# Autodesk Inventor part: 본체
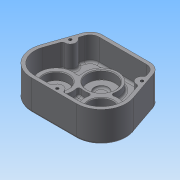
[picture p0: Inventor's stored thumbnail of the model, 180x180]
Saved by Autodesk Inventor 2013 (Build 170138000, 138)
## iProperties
Created: 2014-12
Part Number: 본체
Material: 일반
Document SubType Name: Modeling
Designer: WINDOWS7
Density: 1 g/cm^3
Author: WINDOWS7
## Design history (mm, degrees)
sketch "스케치1" dims "d16" = 46
  geometry: L1 (-47, 36)-(47, 36); L2 (47, 36)-(66.565, -20.803); L3 (32.527, -68.527)-(-32.527, -68.527); L4 (-66.565, -20.803)-(-47, 36); L5 (-32.527, -32.527)-(0, 0); L6 (0, 0)-(32.527, -32.527); L7 (0, 0)-(-87.158, 0); A1 r 36 centre (-32.527, -32.527) between (-32.527, -68.527) and (-66.565, -20.803); A2 r 36 centre (32.527, -32.527) between (66.565, -20.803) and (32.527, -68.527); 2 further points
  constraints: 14 end point, 4 point on circle, 4 tangent, 2 centre point, 2 horizontal, 2 midpoint, 2 vertical alignment, 1 coincident, 1 equal radius, 1 parallel, 3 other
  dimensions: "d8" = 94 distance of L1.start L1.end; "d11" = 36 distance from line of L5.end L1; "d12" = 36 radius of A1; "d13" = 90 deg angle of L6 L5; "d18" = 45 deg angle of L7 L5
extrude "돌출1" new body sketch "스케치1" distance "d19" = 44; taper "d20" = 0 deg
fillet "모깎기1" dims "d21" = 18
sketch "스케치2"
  geometry: L1 (-51.181, 23.862)-(-66.565, -20.803) reference; L2 (-32.527, -68.527)-(32.527, -68.527) reference; L3 (66.565, -20.803)-(51.181, 23.862) reference; L4 (34.162, 36)-(-34.162, 36) reference; L5 (-46.453, 22.233)-(-61.837, -22.432); L6 (-32.527, -63.527)-(32.527, -63.527); L7 (61.837, -22.432)-(46.453, 22.233); L8 (34.162, 31)-(-34.162, 31); A1 r 18 centre (-34.162, 18) between (-34.162, 36) and (-51.181, 23.862) reference; A2 r 36 centre (-32.527, -32.527) between (-66.565, -20.803) and (-32.527, -68.527) reference; A3 r 36 centre (32.527, -32.527) between (32.527, -68.527) and (66.565, -20.803) reference; A4 r 18 centre (34.162, 18) between (51.181, 23.862) and (34.162, 36) reference; A5 r 13 centre (-34.162, 18) between (-34.162, 31) and (-46.453, 22.233); A6 r 31 centre (-32.527, -32.527) between (-61.837, -22.432) and (-32.527, -63.527); A7 r 31 centre (32.527, -32.527) between (32.527, -63.527) and (61.837, -22.432); A8 r 13 centre (34.162, 18) between (46.453, 22.233) and (34.162, 31); 1 further point
  constraints: 8 end point, 8 point on circle, 4 centre point, 7 other
  dimensions: "d22" = 5 distance between parallel lines of L4 L8
extrude "돌출2" cut sketch "스케치2" distance "d23" = 34; taper "d24" = 0 deg
sketch "스케치3"
  geometry: C1 r 24 at (0, 0); C2 r 24 at (-32.527, -32.527); C3 r 24 at (32.527, -32.527); A1 r 31 centre (-32.527, -32.527) between (-61.837, -22.432) and (-32.527, -63.527) reference; A2 r 31 centre (32.527, -32.527) between (32.527, -63.527) and (61.837, -22.432) reference; 1 further point
  constraints: 3 centre point, 3 coincident, 1 equal radius
  dimensions: "d25" = 48 diameter of C1; "d27" = 48 diameter of C3
extrude "돌출3" join sketch "스케치3" distance "d28" = 11; taper "d29" = 0 deg
sketch "스케치4"
  geometry: C1 r 20 at (0, 0); A1 r 24 centre (0, 0) between (21.111, -11.416) and (-21.111, -11.416) reference
  constraints: 1 centre point, 1 coincident
  dimensions: "d30" = 40 diameter of C1
extrude "돌출4" cut sketch "스케치4" distance "d32" = 12; taper "d33" = 0 deg
sketch "스케치5"
  geometry: C1 r 17.5 at (-32.527, -32.527); C2 r 17.5 at (32.527, -32.527); A1 r 24 centre (32.527, -32.527) between (11.416, -21.111) and (21.111, -11.416) reference; A2 r 24 centre (-32.527, -32.527) between (-21.111, -11.416) and (-11.416, -21.111) reference
  constraints: 2 centre point, 2 coincident, 1 equal radius
  dimensions: "d34" = 35 diameter of C2
extrude "돌출5" cut sketch "스케치5" distance "d36" = 11; taper "d37" = 0 deg
sketch "스케치6"
  geometry: C1 r 20 at (0, 0) reference; C2 r 10 at (0, 0)
  constraints: 1 centre point, 1 coincident
  dimensions: "d38" = 20 diameter of C2
extrude "돌출6" cut sketch "스케치6" distance "d40" = 3; taper "d41" = 0 deg
sketch "스케치7"
  geometry: C1 r 20 at (-32.527, -32.527); C2 r 20 at (32.527, -32.527); A1 r 36 centre (-32.527, -32.527) between (-66.565, -20.803) and (-32.527, -68.527) reference; A2 r 36 centre (32.527, -32.527) between (32.527, -68.527) and (66.565, -20.803) reference; 1 further point
  constraints: 2 centre point, 2 coincident, 1 equal radius
  dimensions: "d42" = 40 diameter of C1
extrude "돌출7" join sketch "스케치7" distance "d44" = 7; taper "d45" = -10 deg
sketch "스케치8"
  geometry: C1 r 18.766 at (0, 0) reference; C2 r 15 at (0, 0); C3 r 18.766 at (65.054, 0) reference; C4 r 15 at (65.054, 0); 1 further point
  constraints: 2 centre point, 2 coincident, 1 equal radius
  dimensions: "d46" = 30 diameter of C2
extrude "돌출8" cut sketch "스케치8" distance "d48" = 7; taper "d49" = 0 deg
sketch "스케치9"
  geometry: C1 r 15 at (0, 0) reference; C2 r 7.75 at (0, 0); C3 r 15 at (65.054, 0) reference; C4 r 7.75 at (65.054, 0); 1 further point
  constraints: 2 centre point, 2 coincident, 1 equal radius
  dimensions: "d50" = 15.5 diameter of C2
extrude "돌출9" cut sketch "스케치9" distance "d52" = 10; taper "d53" = 0 deg
sketch "스케치10"
  geometry: L1 (-61.837, -22.432)-(-46.453, 22.233) reference; L2 (46.453, 22.233)-(61.837, -22.432) reference; L3 (32.527, -63.527)-(-32.527, -63.527) reference; L4 (-51.181, 23.862)-(-66.565, -20.803) reference; L5 (-32.527, -68.527)-(32.527, -68.527) reference; L6 (66.565, -20.803)-(51.181, 23.862) reference; L7 (34.162, 36)-(-34.162, 36) reference; A1 r 8 centre (-51.7, 7) between (-58.461, 2.724) and (-54.394, 14.533); A2 r 8 centre (51.7, 7) between (54.394, 14.533) and (58.461, 2.724); A3 r 8 centre (0, -63.527) between (6.245, -68.527) and (-6.245, -68.527); 1 further point
  constraints: 8 point on line, 6 point on circle, 3 centre point, 2 equal radius, 1 horizontal alignment, 1 midpoint
  dimensions: "d54" = 29 distance from line of L7 A2.centre; "d55" = 8 radius of A2
extrude "돌출10" join sketch "스케치10" distance "d56" = 44; taper "d57" = 0 deg
sketch "스케치11"
  geometry: A1 r 8 centre (-51.7, 7) between (-54.305, -0.564) and (-49.095, 14.564) reference; A2 r 8 centre (51.7, 7) between (49.095, 14.564) and (54.305, -0.564) reference; A3 r 8 centre (0, -63.527) between (8, -63.527) and (-8, -63.527) reference; 4 further points
  constraints: 3 coincident
hole "구멍1" sketch "스케치11" at (-51.7, 7), (51.7, 7), (0, -63.527) diameter "d58" = 4.134; stored, may be unused: countersink angle "d62" = 90 deg, drill point angle "d64" = 118 deg; dims "d59" = 20, "d60" = 4, "d61" = 2, "d63" = 23
sketch "스케치12"
  geometry: L1 (-34.162, 36)-(34.162, 36) reference; 3 further points
  constraints: 1 midpoint, 1 vertical alignment, 1 other
  dimensions: "d65" = 30 distance from line of L1 point (0, 6)
extrude "돌출11" join sketch "스케치12" distance "d66" = 1; taper "d67" = 0 deg
chamfer "모따기1" distance "d68" = 1; stored, may be unused: second distance "d69" = 2, angle "d70" = 45 deg
fillet "모깎기2" dims "d71" = 3
fillet "모깎기3" dims "d72" = 3, "d73" = 0.3, "d74" = 0.1
fillet "모깎기4" dims "d75" = 3
node "솔리드1"
node "투영된 루프1"
